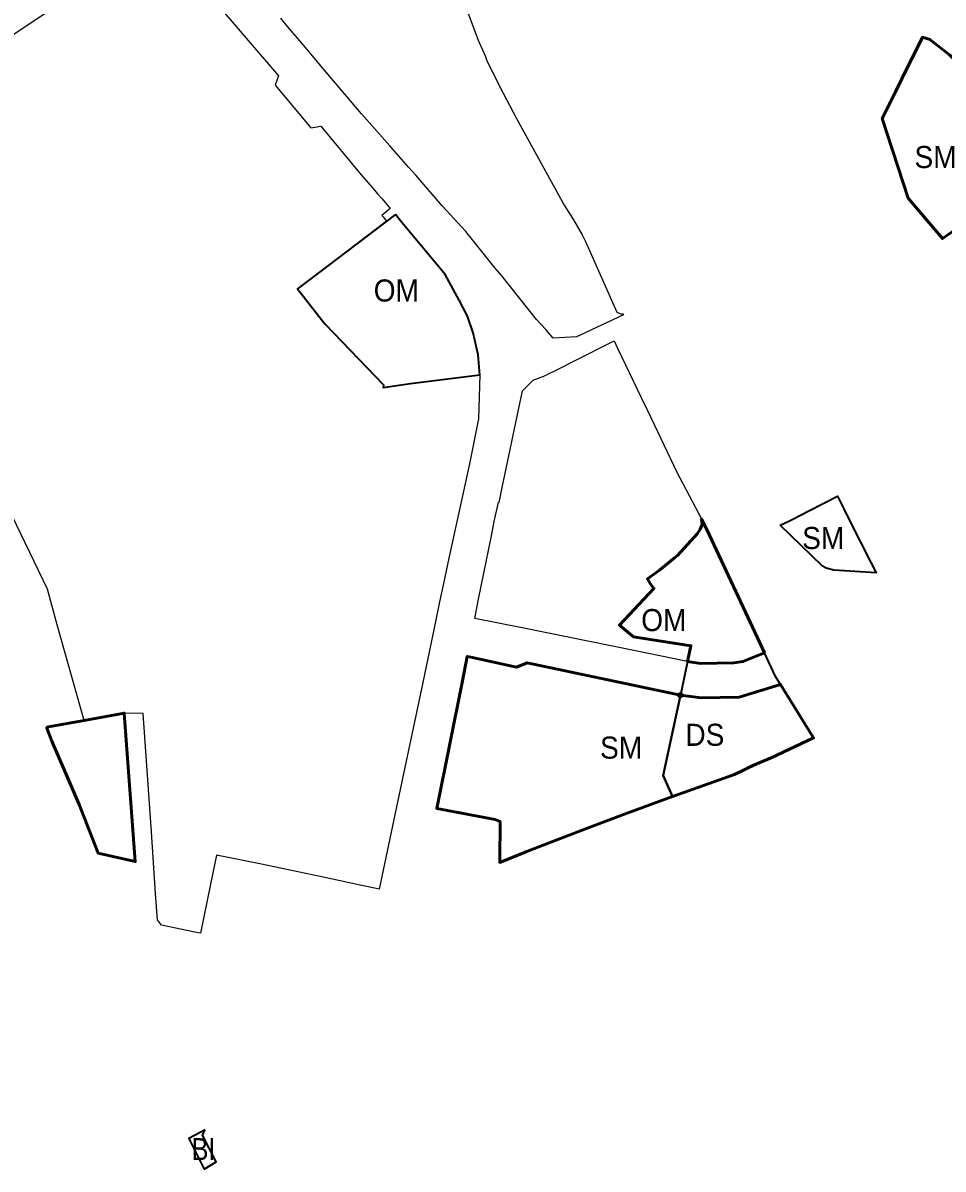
# Model space of a CAD drawing. Extents: x -650276 to -642489, y -1074311 to -1066658.
# Drawn here: x -647429 to -646929, y -1071700 to -1071077 of the extents above; entities that cross this region are included whole.
import ezdxf

# ---------------------------------------------------------------- set-up
doc = ezdxf.new("R2010")
doc.units = 0
doc.header["$LTSCALE"] = 4.8
doc.header["$PDMODE"] = 32
doc.header["$PDSIZE"] = 2.4
for name, color, linetype, lineweight in [('12', 7, 'Continuous', 35), ('15', 7, 'Continuous', 35), ('18', 7, 'Continuous', 35), ('2', 7, 'Continuous', 35), ('24', 7, 'Continuous', 35), ('60', 7, 'Continuous', 53), ('61', 7, 'Continuous', 25)]:
    doc.layers.add(name, color=color, linetype=linetype, lineweight=lineweight)
doc.layers.add('62', color=7, linetype='Continuous')
doc.layers.add('63', color=7, linetype='Continuous')

msp = doc.modelspace()

# ---------------------------------------------------------------- linework, layer by layer
at = {"layer": '12'}
for points in [[(-647226.895, -1071181.511), (-647280.14, -1071221.92), (-647268.52, -1071236.78), (-647265.15, -1071241.1), (-647233.34, -1071274.07), (-647233.64, -1071275.42), (-647218.75, -1071273.32), (-647181.12, -1071268.66), (-647181.99, -1071257.66), (-647184.58, -1071245.67), (-647187.68, -1071236.74), (-647192.29, -1071228.1), (-647199.82, -1071213.98), (-647223.46, -1071185.83)], [(-647056.48, -1071355.32), (-647060.6, -1071346.87), (-647060.22, -1071349.87), (-647061.4, -1071352.51), (-647062.78, -1071354.77), (-647073.68, -1071366.75), (-647075.25, -1071368.01), (-647083.48, -1071374.62), (-647090.04, -1071379.44), (-647088.57, -1071381.97), (-647086.45, -1071384.59), (-647105.2, -1071404.54), (-647097.5, -1071410.96), (-647066.35, -1071415.79), (-647068.162, -1071424.298), (-647061.23, -1071425.434), (-647043.137, -1071424.978), (-647038.119, -1071424.37), (-647026.472, -1071419.614), (-647035.47, -1071400.31)]]:
    msp.add_lwpolyline(points, close=True, dxfattribs=at)
at = {"layer": '15'}
for points in [[(-647072.11, -1071442.6), (-647060.812, -1071444.006), (-647040.089, -1071443.76), (-647017.7, -1071436.79), (-647020.52, -1071432.42), (-647026.472, -1071419.614)], [(-647026.472, -1071419.614), (-647038.119, -1071424.37), (-647043.137, -1071424.978), (-647061.23, -1071425.434), (-647068.162, -1071424.298)], [(-647068.162, -1071424.298), (-647068.162, -1071424.298), (-647072.11, -1071442.6)]]:
    msp.add_lwpolyline(points, dxfattribs=at)
msp.add_point((-647072.11, -1071442.6), dxfattribs=at)
at = {"layer": '18'}
for points in [[(-646951.831, -1071107.765), (-646955.138, -1071114.466), (-646962.471, -1071129.325), (-646948.286, -1071172.534), (-646929.64, -1071194.58), (-646899.85, -1071173.89), (-646881.68, -1071161.83), (-646879.91, -1071161.24), (-646881.97, -1071155.84), (-646887.07, -1071145.66), (-646890.59, -1071140.39), (-646896.62, -1071133.93), (-646904.64, -1071123.54), (-646906.72, -1071120.46), (-646920.54, -1071099.98), (-646925.88, -1071094.68), (-646936.51, -1071086.33), (-646940.67, -1071085.15), (-646940.67, -1071085.15)], [(-647017.93, -1071350.33), (-647013.15, -1071348.01), (-647004.02, -1071343.32), (-647003.37, -1071342.99), (-646993.38, -1071337.85), (-646986.69, -1071334.53), (-646983.33, -1071341.44), (-646977.95, -1071352.38), (-646974.28, -1071359.48), (-646968.63, -1071370.46), (-646965.74, -1071376.18), (-646988.77, -1071374.77), (-646992.95, -1071373.61), (-646994.85, -1071372.49)], [(-647072.11, -1071442.6), (-647155.36, -1071425), (-647161.2, -1071427.33), (-647185.99, -1071421.98), (-647187.85, -1071421.58), (-647190.4, -1071434.75), (-647204.42, -1071504.1), (-647172.74, -1071510.15), (-647170.01, -1071511.22), (-647170.18, -1071532.22), (-647170.23, -1071533.44), (-647155.58, -1071527.62), (-647151.28, -1071525.99), (-647123.17, -1071515.01), (-647104.47, -1071508.08), (-647076.46, -1071497.69), (-647081.488, -1071486.251)]]:
    msp.add_lwpolyline(points, close=True, dxfattribs=at)
at = {"layer": '2'}
for points in [[(-647330.34, -1071678.82), (-647339.211, -1071683.431), (-647330.73, -1071700.09)], [(-647330.73, -1071700.09), (-647324.21, -1071696.2), (-647331.65, -1071681.7), (-647330.34, -1071678.82)]]:
    msp.add_lwpolyline(points, dxfattribs=at)
at = {"layer": '24'}
msp.add_line((-647081.488, -1071486.251), (-647076.46, -1071497.69), dxfattribs=at)
for points in [[(-647017.7, -1071436.79), (-647040.089, -1071443.76), (-647060.812, -1071444.006), (-647072.11, -1071442.6), (-647081.488, -1071486.251)], [(-647076.46, -1071497.69), (-647042.78, -1071485.76), (-647022.81, -1071476.61), (-646999.77, -1071465.81), (-647017.7, -1071436.79)]]:
    msp.add_lwpolyline(points, dxfattribs=at)
at = {"layer": '60'}
for points in [[(-646951.831, -1071107.765), (-646955.138, -1071114.466), (-646962.471, -1071129.325), (-646948.286, -1071172.534), (-646929.64, -1071194.58), (-646899.85, -1071173.89), (-646881.68, -1071161.83), (-646879.91, -1071161.24), (-646881.97, -1071155.84), (-646887.07, -1071145.66), (-646890.59, -1071140.39), (-646896.62, -1071133.93), (-646904.64, -1071123.54), (-646906.72, -1071120.46), (-646920.54, -1071099.98), (-646925.88, -1071094.68), (-646936.51, -1071086.33), (-646940.67, -1071085.15)], [(-647056.48, -1071355.32), (-647060.6, -1071346.87), (-647060.22, -1071349.87), (-647061.4, -1071352.51), (-647062.78, -1071354.77), (-647073.68, -1071366.75), (-647075.25, -1071368.01), (-647083.48, -1071374.62), (-647090.04, -1071379.44), (-647088.57, -1071381.97), (-647086.45, -1071384.59), (-647105.2, -1071404.54), (-647097.5, -1071410.96), (-647066.35, -1071415.79), (-647068.162, -1071424.298), (-647061.23, -1071425.434), (-647043.137, -1071424.978), (-647038.119, -1071424.37), (-647026.472, -1071419.614), (-647035.47, -1071400.31)], [(-647072.11, -1071442.6), (-647155.36, -1071425), (-647161.2, -1071427.33), (-647185.99, -1071421.98), (-647187.85, -1071421.58), (-647190.4, -1071434.75), (-647204.42, -1071504.1), (-647172.74, -1071510.15), (-647170.01, -1071511.22), (-647170.18, -1071532.22), (-647170.23, -1071533.44), (-647155.58, -1071527.62), (-647151.28, -1071525.99), (-647123.17, -1071515.01), (-647104.47, -1071508.08), (-647076.46, -1071497.69), (-647042.78, -1071485.76), (-647038.62, -1071483.74), (-647033.09, -1071481.06), (-647032.73, -1071480.88), (-647022.81, -1071476.61), (-646999.77, -1071465.81), (-647017.7, -1071436.79), (-647040.089, -1071443.76), (-647060.812, -1071444.006)], [(-647416.42, -1071460.03), (-647396.02, -1071456.32), (-647374.2, -1071452.36), (-647368.26, -1071532.99), (-647388.29, -1071528.41), (-647398.64, -1071501.96), (-647413.54, -1071467.53)]]:
    msp.add_lwpolyline(points, close=True, dxfattribs=at)
at = {"layer": '61'}
for points in [[(-647442.36, -1071088.82), (-647406.52, -1071065.05)], [(-647324.46, -1071066.41), (-647290.44, -1071106.08), (-647292.31, -1071111.16), (-647272.8, -1071134.42), (-647267.4, -1071133.54), (-647245.43, -1071159.88), (-647239.35, -1071166.98), (-647236.41, -1071170.41), (-647234.12, -1071172.97), (-647229.71, -1071178.23), (-647234.22, -1071182.02), (-647233.57, -1071182.82), (-647231.69, -1071185.15), (-647262.35, -1071208.42), (-647263.8, -1071209.52), (-647278.04, -1071220.33), (-647280.14, -1071221.92), (-647268.52, -1071236.78), (-647265.15, -1071241.1), (-647233.34, -1071274.07), (-647233.64, -1071275.42), (-647209.66, -1071272.22), (-647181.12, -1071268.66), (-647181.79, -1071292.49), (-647186.6, -1071316.98), (-647197.87, -1071368.22), (-647200.76, -1071382.02), (-647202.98, -1071391.98), (-647205.52, -1071404.32), (-647212.07, -1071435.71), (-647226.296, -1071503.249), (-647235.71, -1071547.94), (-647248.51, -1071545.3), (-647265.23, -1071541.68), (-647278.94, -1071538.77), (-647300.51, -1071534.33), (-647324.04, -1071529.54), (-647327.31, -1071545.25), (-647332.86, -1071571.94), (-647335.88, -1071571.31), (-647353.95, -1071567.53), (-647356.2, -1071564.75), (-647357.15, -1071550.44), (-647359.38, -1071516.88), (-647363.86, -1071452.66), (-647374.2, -1071452.36), (-647396.02, -1071456.32), (-647410.56, -1071404.35), (-647415.97, -1071385.01), (-647445, -1071324.99)], [(-647189.68, -1071065.99), (-647181.99, -1071086.74), (-647178.11, -1071095.31), (-647177.46, -1071097.42), (-647170.18, -1071112.08), (-647161.13, -1071129.3), (-647146.28, -1071156.35), (-647135.21, -1071176.44), (-647130.1, -1071184.33), (-647125.44, -1071192.58), (-647123.7, -1071196.19), (-647106.7, -1071234.45), (-647104.17, -1071235.6), (-647103.31, -1071235.22), (-647102.97, -1071235.92), (-647126.477, -1071247.083), (-647128.45, -1071248.02), (-647141.14, -1071248.62), (-647145.16, -1071243.92), (-647150.32, -1071238.51), (-647169.11, -1071214.8), (-647172.63, -1071210.63), (-647188.68, -1071190.78), (-647201.42, -1071176.7), (-647215.86, -1071160.1), (-647219.82, -1071155.78), (-647229.97, -1071144.1), (-647231.32, -1071142.57), (-647238.29, -1071134.66), (-647245.31, -1071126.75), (-647257.41, -1071112.55), (-647267.64, -1071100.44), (-647272.93, -1071094.24), (-647278.77, -1071087.15), (-647285.53, -1071079.39), (-647289.1, -1071074.88)]]:
    msp.add_lwpolyline(points, dxfattribs=at)
msp.add_lwpolyline([(-647093.11, -1071411.77), (-647066.35, -1071415.79), (-647068.162, -1071424.298), (-647097.427, -1071418.318), (-647157.231, -1071406.28), (-647183.816, -1071400.974), (-647181.75, -1071390.51), (-647174.73, -1071356.1), (-647173.24, -1071348.27), (-647170.96, -1071337.84), (-647170.63, -1071337.91), (-647168.91, -1071329.88), (-647157.83, -1071277.35), (-647152.09, -1071271.47), (-647146.3, -1071269.33), (-647137.84, -1071265.06), (-647130.76, -1071261.49), (-647108.16, -1071250.08), (-647106.233, -1071254.01), (-647093.39, -1071280.83), (-647090, -1071287.89), (-647079.25, -1071310.33), (-647073.98, -1071321.53), (-647060.6, -1071346.87), (-647060.22, -1071349.87), (-647061.4, -1071352.51), (-647062.78, -1071354.77), (-647073.68, -1071366.75), (-647075.25, -1071368.01), (-647083.48, -1071374.62), (-647083.48, -1071374.62), (-647090.04, -1071379.44), (-647086.45, -1071384.59), (-647105.2, -1071404.54), (-647097.5, -1071410.96)], close=True, dxfattribs=at)

# ---------------------------------------------------------------- texts
at = {"layer": '62'}
for s, width, p in [('OM', 0.95, (-647238.703, -1071228.756)), ('SM', 0.95, (-647005.938, -1071363.245)), ('OM', 0.95, (-647093.38, -1071407.817)), ('DS', 0.95, (-647069.386, -1071470.148)), ('SM', 0.95, (-647115.735, -1071477.109)), ('BI', 0.85, (-647337.578, -1071695.247))]:
    msp.add_text(s, height=12, dxfattribs=dict(at, width=width)).set_placement(p)
at = {"layer": '63', "width": 0.95}
msp.add_text('SM', height=12, dxfattribs=at).set_placement((-646944.938, -1071156.245))

doc.saveas('drawing.dxf')
